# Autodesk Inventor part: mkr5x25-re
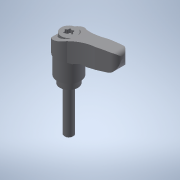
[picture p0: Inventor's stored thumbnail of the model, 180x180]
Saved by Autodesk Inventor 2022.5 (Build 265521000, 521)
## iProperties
Created: 2017-09
Part Number: mkr5x25-re
Material: 一般
Document SubType Name: Modeling
Designer: imaocorp
Density: 1 g/cm^3
Appearance: 既定
Author: imaocorp
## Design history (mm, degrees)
node "mkr5x25-re.x_t1"
node "mkr5x25-re"
node "Base1"
